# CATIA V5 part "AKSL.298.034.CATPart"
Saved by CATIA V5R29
Part number: АКСЛ.298.034
Definition: Уголок 200 мм
Publications: "Грань по длине шипа", "Грань по ширине шипа", "Грань по длине шипа1", "Грань по ширине шипа1"
Material "Steel": density 7860 kg/m3, Young's modulus 2e+11 Pa, Poisson ratio 0.266, thermal expansion 1.17e-05 1/K
Bounding box of the stored display mesh (mm): x -70.633 to 14.166, y -71.391 to 71.658, z -98 to 98
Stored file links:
  Z:\ООО Аксель\Соединения бруса\Соединения бруса\Соединения из листа\АКСЛ.298.030 (Трио)\AKSL.298.034.CATPart
  Z:\ООО Аксель\Соединения бруса\Соединения бруса\Соединения из листа\АКСЛ.298.030 (Трио)\AKSL.298.030.CATProduct
  Z:\#Catalog_GosNIIAS\Holes&Pockets\Part\Соединение шип-паз\Ship-Paz.CATPart
  Z:\ООО Аксель\Соединения бруса\Соединения бруса\Соединения из листа\АКСЛ.298.020 (Дуо)\AKSL.298.020.Skelet.CATPart
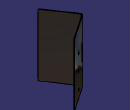
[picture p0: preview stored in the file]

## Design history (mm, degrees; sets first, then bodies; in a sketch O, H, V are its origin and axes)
External parameters (linked from other documents)
  `External.S металла` = 2 mm
  `External.R гиба` = 1.9 mm
  `External.K factor` = 0.49
  `External.S металла.1` = 2 mm
SheetMetalParameters1: Thickness 2 {= `External.S металла`}, BendRadius 1.9 {= `External.R гиба`}, KFactor 0.49 {= `External.K factor`}, ReliefRadialLength 1, ReliefAxialLength 2, MinimumBendRadius 0
Set1 "Шип в центре грани"
  Extract1 "Плоскость шипа": ExtractElem face of Wall2
  Extract2 "Грань по длине шипа": ExtractElem edge of Extract1
  Extract3 "Грань по ширине шипа": ExtractElem edge of Extract1
Set2 "Шип в центре грани"
  Extract4 "Плоскость шипа": ExtractElem face of Wall1
  Extract5 "Грань по длине шипа": ExtractElem edge of Extract4
  Extract6 "Грань по ширине шипа": ExtractElem edge of Extract4
Set3
  DatumSurface1: linked copy from another document
  DatumCurve1 to DatumCurve4: linked copy from another document
Body1 (main body)
  ThickSurface1: BotOffset 0, Surface DatumSurface1, TopOffset 2 {= `External.S металла`}
  Recognize1: Recognize_BendTable SheetMetalParameters1, Recognize_ReferenceFace face of ThickSurface1, Recognize_BendDefaultRadius 1.9 {= `External.R гиба`}, KFacteur 0.49 {= SheetMetalParameters1.KFactor}
  d_Bend1: Bend_BendTable SheetMetalParameters1, Bend_Thickness 2 {= `External.S металла`}, Bend_KFactor 0.49 {= SheetMetalParameters1.KFactor}, Bend_FirstSupport face of Recognize1, Bend_SecondSupport face of Recognize1, Bend_KFactorRadius 1.9 {= d_Bend1.CylindricalBendSurf_Radius}, Bend_Deduction -3.2761 {= (d_Bend1.CylindricalBendSurf_Radius+SheetMetalParameters1.Thickness*d_Bend1.Bend_KFactor)*(PI-abs(d_Bend1.BendSurf_OpenAngle))-2*(d_Bend1.CylindricalBendSurf_Radius+SheetMetalParameters1.Thickness)*tan(min((PI-abs(d_Bend1.BendSurf_OpenAngle)),(PI/2))/2)}
  Sketch1 on face of Recognize1, origin (6468.956, 4447.1124, -53.2742), H (-0.8278, -0.561, 0), V (0, 0, 1)
    point P1 (7849.9361, -19.7258)
    reference projected line E1 (7797.9361, -44.7258) -> (7797.9361, 151.2742) from edge [face of Recognize1 | face of Recognize1]
    reference projected line E2 (7901.9361, -44.7258) -> (7901.9361, 151.2742) from face of Recognize1
    construction line L1 (7797.9361, -44.7258) -> (7901.9361, -44.7258)
    distance P1 L1 = 25
    horizontal: L1 H
    equidistance: E2 E1 P1
  Hole1: placed by Sketch1, at (-29.1737, 43.0453, -73) direction (0.561, -0.8278, 0), diameter 8, through (limit type 6)
  RectPattern1: of Hole1, direction 1 instances 3, spacing 50, along edge [face of Recognize1 | face of Recognize1]
  CutOut1: Direction Sketch3, EndLimit through (limit type 2), Orientation true, Profile Sketch3, StartLimit through (limit type 2)
  Wall1: Thickness 2 {= `External.S металла`}, Profile Sketch4, ListTangentTo face of Recognize1, OffsetValue 0
  CutOut2: Direction Sketch5, EndLimit through (limit type 2), Orientation true, Profile Sketch5, StartLimit through (limit type 2)
  CutOut3: Direction Sketch2, EndLimit through (limit type 2), Orientation true, Profile Sketch2, StartLimit through (limit type 2), Thickness1 2, Thickness2 2
  SHM_Mirror1: MirroringPlane xy-plane, ObjectToMirror CutOut3
  Wall2: Thickness 2 {= `External.S металла`}, Profile Sketch6, OffsetValue 0
  Sketch2 on face of Recognize1, origin (133.1737, 153.0752, 0), H (-0.8278, -0.561, 0), V (0, 0, 1)
    construction line L1 (144.1205, -90.5) -> (-38, -90.5)
    construction line L2 (144.1205, -98) -> (-27, -98)
    line L3 (144.1205, -98) -> (145.1205, -98)
    line L4 (145.1205, -98) -> (145.1205, -90.5)
    line L5 (145.1205, -90.5) -> (144.1205, -90.5)
    line L6 (144.1205, -90.5) -> (144.1205, -98)
    point P6 (145.1205, -90.5)
    distance L4 L6 = 1
    horizontal: L1 H, L2 H, L3 H, L5 H
    vertical: L4 V, L6 V
    coincidence: P6 L1
  Sketch3 on DatumCurve1, origin (-58.68, 20.6315, -23.9612), H (0, 0, 1), V (0.8278, 0.561, 0)
    reference projected line E1 (0, -3) -> (0, 0) from DatumCurve2
    reference projected line E2 (0, 0) -> (50, 0) from DatumCurve1
    construction line L1 (0, -1.5) -> (25, -1.5)
    point P5 (0, -1.5)
    point P6 (25, -1.5)
    axis line L2 (25, 0) -> (25, 7.3468)
    point P7 (25, 0)
    line L3 (50.1, -3.1) -> (50.1, 0.1)
    line L4 (50.1, 0.1) -> (-0.1, 0.1)
    line L5 (-0.1, 0.1) -> (-0.1, -3.1)
    line L6 (-0.1, -3.1) -> (50.1, -3.1)
    distance L5 E1 = 0.1
    distance E2 L4 = 0.1
    midpoint: P5 E1, P7 E2
    coincidence: L2 P6
    equidistance: L3 L5 P6, L4 L6 P6
    parallelism: L1 E2, L2 E1, L6 L4, L3 L5
  Sketch4 on face of Recognize1, origin (-123.9015, 90.1284, 0), H (0.561, -0.8278, 0), V (0, 0, 1)
    reference projected line E1 (194.1205, 98) -> (194.1205, -98) from edge [face of Recognize1 | face of Recognize1]
    line L1 (195.1205, -90) -> (194.1205, -90)
    line L2 (194.1205, -90) -> (194.1205, 90)
    line L3 (194.1205, 90) -> (195.1205, 90)
    line L4 (195.1205, 90) -> (195.1205, -90)
    axis line L5 (194.1205, 0) -> (195.1205, 0)
    point P7 (194.1205, 0)
    point P8 (195.1205, 0)
    distance L2 L4 = 1 {= `External.S металла` /2}
    distance L1 L3 = 180
    length E1 = 196 (reference)
    perpendicularity: L2 L1
    midpoint: P7 L2, P8 L4, P7 E1
    coincidence: L2 E1
  Sketch5 on DatumCurve3, origin (12.7771, 70.2691, -90), H (0, 0, -1), V (0.8278, 0.561, 0)
    reference projected line E1 (0, 0) -> (0, 2) from DatumCurve4
    reference projected line E2 (-180, 0) -> (0, 0) from DatumCurve3
    construction line L1 (0, 1) -> (-90, 1)
    point P5 (0, 1)
    point P6 (-90, 1)
    axis line L2 (-90, 0) -> (-90, 7.3468)
    point P7 (-90, 0)
    line L3 (-180.5, 2) -> (-180.5, 0)
    line L4 (-180.5, 0) -> (0.5, 0)
    line L5 (0.5, 0) -> (0.5, 2)
    line L6 (0.5, 2) -> (-180.5, 2)
    distance L5 E1 = 0.5
    distance E2 L4 = 0
    midpoint: P5 E1, P7 E2
    coincidence: L2 P6
    equidistance: L3 L5 P6, L4 L6 P6
    parallelism: L1 E2, L2 E1, L6 L4, L3 L5
  Sketch6 on face of Recognize1, origin (50, -162.8956, 0), H (-0.561, 0.8278, 0), V (0, 0, 1)
    line L1 (111.8956, 90) -> (112.8956, 90)
    line L2 (112.8956, 90) -> (112.8956, -90)
    line L3 (112.8956, -90) -> (111.8956, -90)
    line L4 (111.8956, -90) -> (111.8956, 90)
    axis line L5 (112.8956, 0) -> (111.8956, 0)
    point P5 (112.8956, 0)
    point P6 (111.8956, 0)
    reference projected line E1 (112.8956, -98) -> (112.8956, -90) from edge [face of Recognize1 | face of Recognize1]
    point P7 (112.8956, -98)
    distance L2 L4 = 1 {= `External.S металла.1` /2}
    distance L1 L3 = 180
    distance L3 P7 = 8
    perpendicularity: L2 L1
    midpoint: P5 L2, P6 L4
    coincidence: L2 E1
